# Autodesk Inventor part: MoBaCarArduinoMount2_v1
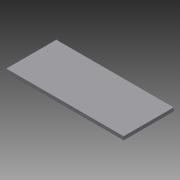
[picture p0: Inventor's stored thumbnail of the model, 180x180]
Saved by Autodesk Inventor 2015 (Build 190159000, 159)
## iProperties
Created: 2017-05
Part Number: MoBaCarArduinoMount2_v1
Material: Generisch
Document SubType Name: Modeling
Designer: Andreas
Density: 1 g/cm^3
Appearance: Vorgabe
Author: Andreas
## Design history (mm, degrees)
sketch "Skizze1"
  geometry: L1 (0, 0)-(169, 0); L2 (169, 0)-(169, 72); L3 (169, 72)-(0, 72); L4 (0, 72)-(0, 0)
  constraints: 8 end point, 2 parallel, 1 horizontal, 1 perpendicular
  dimensions: "d0" = 169 distance of L3.end L2.end; "d1" = 72 distance of L2.end L1.end
extrude "Extrusion1" new body sketch "Skizze1" distance "d2" = 5; taper "d3" = 0 deg
node "Volumenkörper1"
